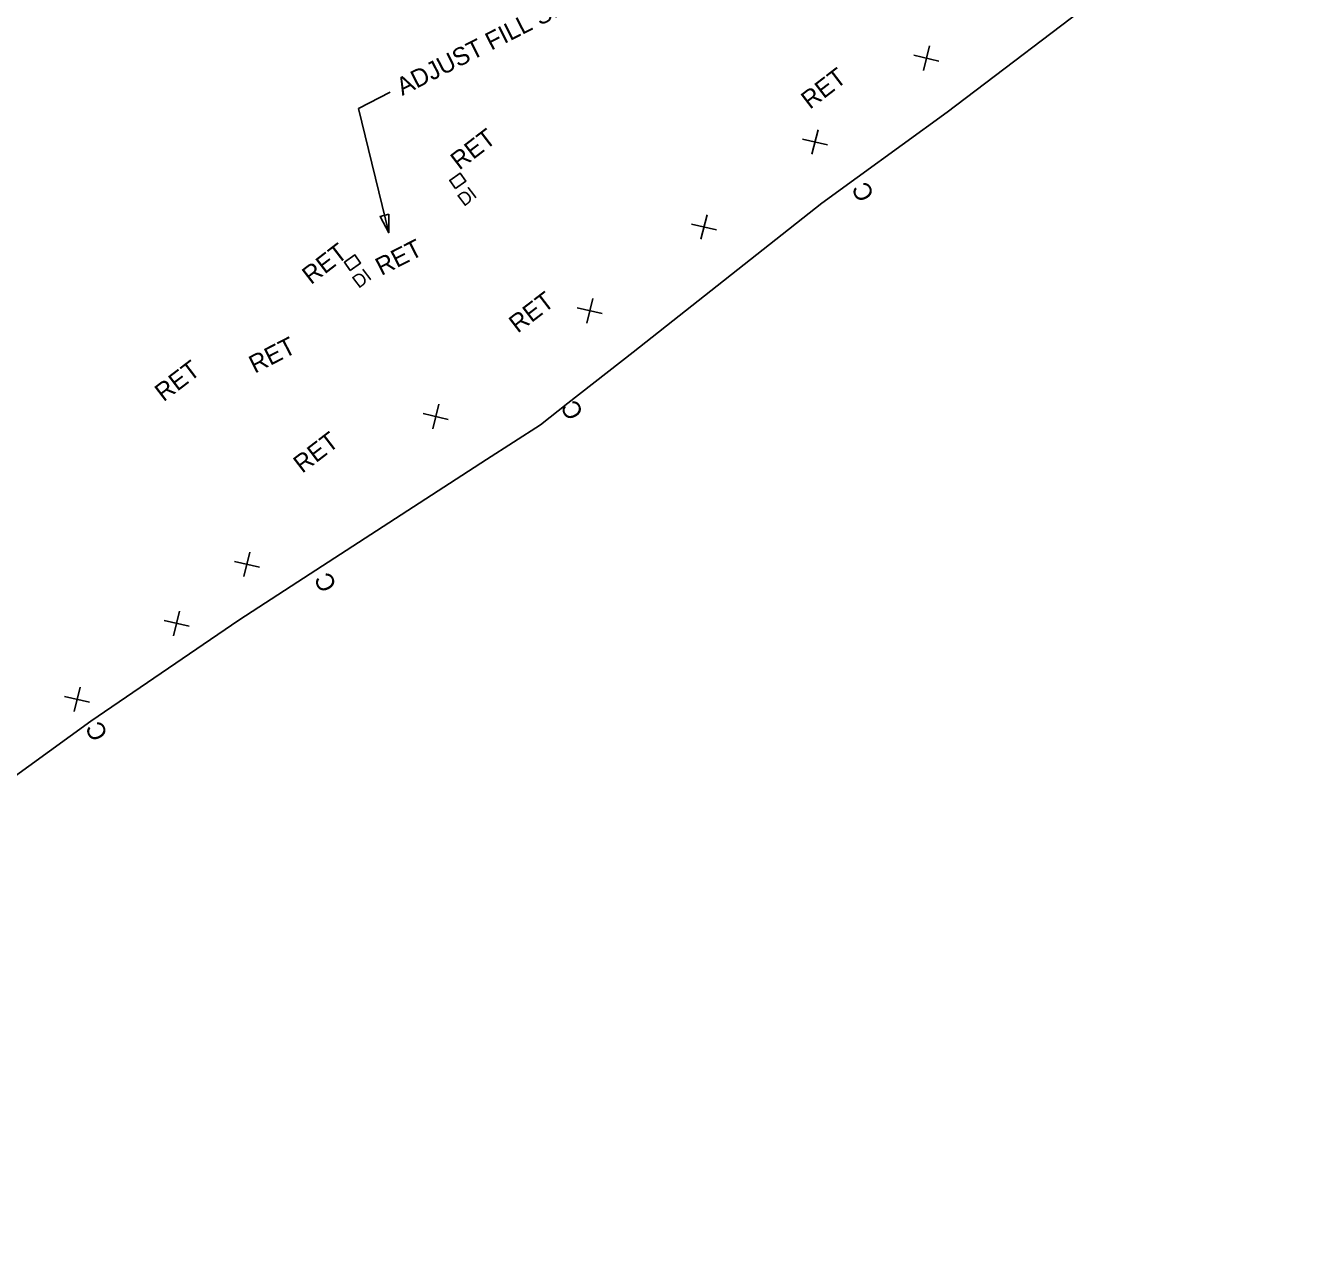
# Model space of a CAD drawing. Extents: x 2384780 to 2405432, y 547869 to 573706.
# Drawn here: x 2403130.2 to 2403485.8, y 570489.3 to 570830.5 of the extents above; entities that cross this region are included whole.
import ezdxf

# ---------------------------------------------------------------- set-up
doc = ezdxf.new("R2010")
doc.units = 0
for name, color, linetype in [('Old_Level_1', 7, 'Continuous'), ('Old_Level_10', 7, 'Continuous'), ('Old_Level_26', 7, 'Continuous'), ('Old_Level_5', 7, 'Continuous'), ('Old_Level_63', 7, 'Continuous')]:
    doc.layers.add(name, color=color, linetype=linetype)

# ---------------------------------------------------------------- blocks, each defined once
blk = doc.blocks.new('SPOT')
at = {"layer": 'Old_Level_1'}
for p, q in [((-5.48625, 4.61225), (5.48625, -4.61175)), ((-4.608, -5.326), (4.609, 5.325))]:
    blk.add_line(p, q, dxfattribs=at)

msp = doc.modelspace()

# ---------------------------------------------------------------- linework, layer by layer
at = {"layer": 'Old_Level_10'}
for points in [[(2403250.33, 570785.03), (2403248.73, 570787.28), (2403251.62, 570789.33), (2403253.22, 570787.07)], [(2403220.92, 570762.16), (2403219.32, 570764.41), (2403222.22, 570766.46), (2403223.81, 570764.2)]]:
    msp.add_lwpolyline(points, close=True, dxfattribs=at)
at = {"layer": 'Old_Level_63'}
for p in [(2403232.1, 570811.92), (2403231.67, 570772.67)]:
    msp.add_line(p, (2403223.19, 570807.38), dxfattribs=at)
msp.add_lwpolyline([(2402948.22, 570489.29), (2402987.25, 570518.26), (2402980.89, 570513.54), (2403027.22, 570547.93), (2403066.84, 570578.43), (2403070.31, 570580.83), (2403070.31, 570580.83), (2403107.99, 570606.93), (2403148.49, 570636.3), (2403189.85, 570664.52), (2403206.26, 570675.15), (2403259.01, 570709.32), (2403274.05, 570719.06), (2403281.69, 570725.04), (2403299.95, 570739.33), (2403352.66, 570780.89), (2403362.53, 570788.06), (2403387.63, 570806.3), (2403432.83, 570840.68), (2403472.8, 570870.72), (2403512.01, 570901.75)], dxfattribs=at)
msp.add_lwpolyline([(2403231.69, 570777.82), (2403231.67, 570772.67), (2403229.27, 570777.23)], close=True, dxfattribs=at)

# ---------------------------------------------------------------- block references
at = {"layer": 'Old_Level_63', "xscale": 0.5, "yscale": 0.5, "rotation": 26.999941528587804}
for p in [(2403381.86, 570821.42), (2403350.74, 570798.02), (2403319.73, 570774.29), (2403287.82, 570750.88), (2403244.81, 570721.35), (2403192.08, 570680.08), (2403172.43, 570663.57), (2403144.65, 570642.4)]:
    msp.add_blockref('SPOT', p, dxfattribs=at)

# ---------------------------------------------------------------- texts
at = {"layer": 'Old_Level_26'}
for p in [(2403252.68, 570779.84), (2403223.28, 570756.97)]:
    msp.add_text('DI', height=3.691, rotation=37.3179, dxfattribs=at).set_placement(p)
at = {"layer": 'Old_Level_5'}
for rotation, p in [(37.5142, (2403349.31, 570806.98)), (37.4388, (2403251.39, 570790.01)), (37.5743, (2403209.95, 570758.02)), (26.9999, (2403229.62, 570760.57)), (37.5142, (2403267.7, 570744.47)), (26.9999, (2403194.26, 570733.29)), (37.3739, (2403168.78, 570725.31)), (37.5142, (2403207.51, 570705.33))]:
    msp.add_text('RET', height=5, rotation=rotation, dxfattribs=at).set_placement(p)
at = {"layer": 'Old_Level_63'}
for s, rotation, p in [('ADJUST FILL SLOPE', 26.9999, (2403235.46, 570810.83)), ('C', 118, (2403367.47, 570783.11)), ('C', 118, (2403286.22, 570722.18)), ('C', 118, (2403217.33, 570674.06)), ('C', 118, (2403153.42, 570632.5))]:
    msp.add_text(s, height=5, rotation=rotation, dxfattribs=at).set_placement(p)

doc.saveas('drawing.dxf')
